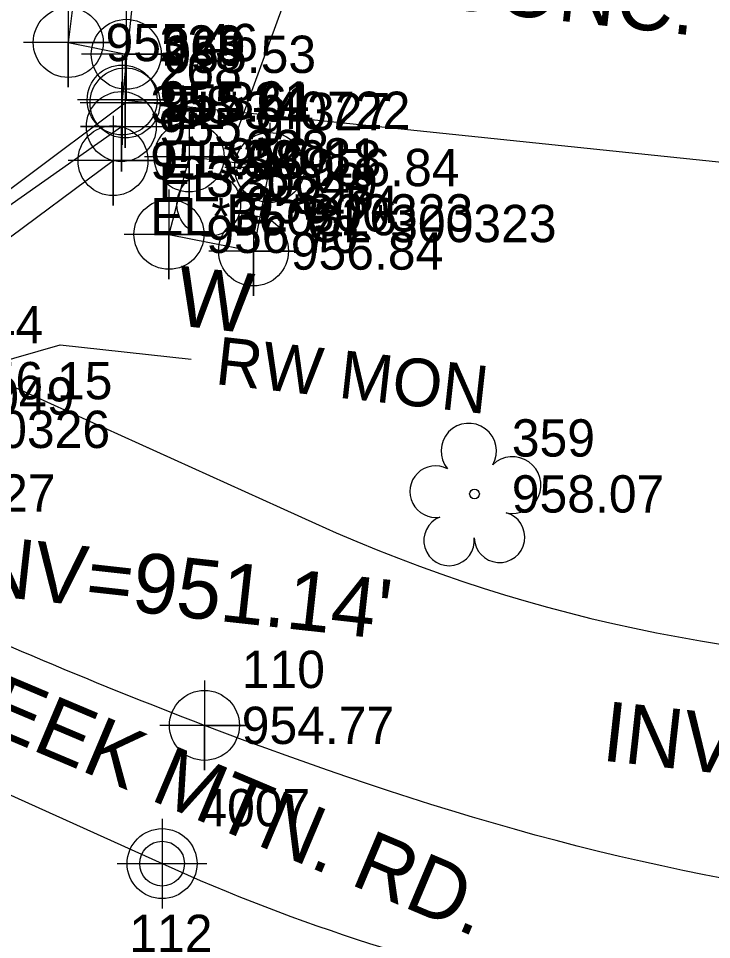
# Model space of a CAD drawing. Extents: x 1150279 to 1151282, y 654632 to 657999.
# Drawn here: x 1150952.8 to 1150999.3, y 657073.4 to 657135.2 of the extents above; entities that cross this region are included whole.
import ezdxf

# ---------------------------------------------------------------- set-up
doc = ezdxf.new("R2010")
doc.units = 0
for name, color, linetype in [('COGO Default Chain', 7, 'Continuous'), ('COGO Default Curve', 7, 'Continuous'), ('Cogo Default Point CELL', 7, 'Continuous'), ('COGO Default Point Number', 7, 'Continuous'), ('Exist Building', 7, 'Continuous'), ('Exist Building Cogo Elevation', 7, 'Continuous'), ('Exist Building Cogo Number', 7, 'Continuous'), ('Exist Building Cogo Point CELL', 7, 'Continuous'), ('Exist Building Steps', 7, 'Continuous'), ('Exist Building Steps Cogo Comment', 7, 'Continuous'), ('Exist Building Steps Cogo Elevation', 7, 'Continuous'), ('Exist Building Steps Cogo Point CELL', 7, 'Continuous'), ('Exist Horizontal Alignment', 7, 'Continuous'), ('Exist Horizontal Alignment Station Label', 7, 'Continuous'), ('Exist Other Culture Well CELL', 7, 'Continuous'), ('Exist Other Culture Well Cogo Elevation', 7, 'Continuous'), ('Exist Other Culture Well Cogo Number', 7, 'Continuous'), ('Exist Other Culture Well Text', 7, 'Continuous'), ('Exist Right of Way Line', 7, 'Continuous'), ('Exist Right of Way Monument Cogo Elevation', 7, 'Continuous'), ('Exist Right of Way Monument Cogo Number', 7, 'Continuous'), ('Exist Right of Way Monument Leader', 7, 'Continuous'), ('Exist Right of Way Monument Text', 7, 'Continuous'), ('Exist Roads Curbs', 7, 'Continuous'), ('Exist Roads Curbs Cogo Comment', 7, 'Continuous'), ('Exist Roads Curbs Cogo Elevation', 7, 'Continuous'), ('Exist Roads Curbs Cogo Number', 7, 'Continuous'), ('Exist Roads Curbs Cogo Point CELL', 7, 'Continuous'), ('Exist Roads EOP', 7, 'Continuous'), ('Exist Roads EOP Cogo Comment', 7, 'Continuous'), ('Exist Roads EOP Cogo Elevation', 7, 'Continuous'), ('Exist Roads EOP Cogo Number', 7, 'Continuous'), ('Exist Roads EOP Cogo Point CELL', 7, 'Continuous'), ('Exist Roads EOP Leader', 7, 'Continuous'), ('Exist Roads EOP Other', 7, 'Continuous'), ('Exist Roads EOP Other Cogo Comment', 7, 'Continuous'), ('Exist Roads EOP Other Cogo Elevation', 7, 'Continuous'), ('Exist Roads EOP Other Cogo Number', 7, 'Continuous'), ('Exist Roads EOP Other Cogo Point CELL', 7, 'Continuous'), ('Exist Roads EOP Text', 7, 'Continuous'), ('Exist Structure Minor Pipes CMP 15 Inch Text', 7, 'Continuous'), ('Exist Structure Minor Pipes CMP 18 Inch Cogo Comment', 7, 'Continuous'), ('Exist Vegetation Hedge Row', 7, 'Continuous'), ('Exist Vegetation Hedge Row Cogo Comment', 7, 'Continuous'), ('Exist Vegetation Hedge Row Cogo Elevation', 7, 'Continuous'), ('Exist Vegetation Hedge Row Cogo Number', 7, 'Continuous'), ('Exist Vegetation Hedge Row Cogo Point CELL', 7, 'Continuous'), ('Exist Vegetation Tree CELL', 7, 'Continuous'), ('Exist Vegetation Tree Cogo Elevation', 7, 'Continuous'), ('Exist Vegetation Tree Cogo Number', 7, 'Continuous')]:
    doc.layers.add(name, color=color, linetype=linetype)

msp = doc.modelspace()

# ---------------------------------------------------------------- linework, layer by layer
at = {"layer": 'COGO Default Chain'}
msp.add_line((1150875.785, 657117.706), (1150962.476, 657078.528), dxfattribs=at)
msp.add_arc((1151016.013, 657196.992), 130, 245.68044, 271.91872, dxfattribs=at)
at = {"layer": 'COGO Default Curve'}
msp.add_arc((1151016.013, 657196.992), 130, 245.68044, 271.91872, dxfattribs=at)
at = {"layer": 'Cogo Default Point CELL'}
for points in [[(1150962.476, 657081.528), (1150962.476, 657078.528)], [(1150962.476, 657081.528), (1150962.476, 657078.528)], [(1150959.476, 657078.528), (1150962.476, 657078.528)], [(1150959.476, 657078.528), (1150962.476, 657078.528)], [(1150962.476, 657078.528), (1150965.476, 657078.528)], [(1150962.476, 657078.528), (1150962.476, 657075.528)], [(1150962.476, 657078.528), (1150965.476, 657078.528)], [(1150962.476, 657078.528), (1150962.476, 657075.528)]]:
    msp.add_lwpolyline(points, dxfattribs=at)
msp.add_circle((1150962.476, 657078.528), 2.344, dxfattribs=at)
msp.add_circle((1150962.476, 657078.528), 2.344, dxfattribs=at)
at = {"layer": 'Exist Building'}
msp.add_lwpolyline([(1150963.173, 657162.304), (1150961.996, 657151.199), (1150955.742, 657152.172), (1150954.56, 657141.15), (1150960.937, 657140.596), (1150959.8, 657129.688), (1151003.45, 657125.164), (1151002.473, 657115.197), (1151037.798, 657111.576), (1151043.238, 657164.141)], dxfattribs=at)
at = {"layer": 'Exist Building Cogo Point CELL'}
msp.add_lwpolyline([(1150959.8, 657132.688), (1150959.8, 657126.688), (1150959.8, 657129.688), (1150962.8, 657129.688), (1150956.8, 657129.688)], dxfattribs=at)
msp.add_circle((1150959.8, 657129.688), 2.344, dxfattribs=at)
at = {"layer": 'Exist Building Steps'}
msp.add_lwpolyline([(1150957.09, 657140.886), (1150956.186, 657133.538), (1150960.076, 657132.748)], dxfattribs=at)
at = {"layer": 'Exist Building Steps Cogo Point CELL'}
for points in [[(1150956.186, 657136.538), (1150956.186, 657130.538), (1150956.186, 657133.538), (1150959.186, 657133.538), (1150953.186, 657133.538)], [(1150960.076, 657135.748), (1150960.076, 657129.748), (1150960.076, 657132.748), (1150963.076, 657132.748), (1150957.076, 657132.748)]]:
    msp.add_lwpolyline(points, dxfattribs=at)
for centre in [(1150956.186, 657133.538), (1150960.076, 657132.748)]:
    msp.add_circle(centre, 2.344, dxfattribs=at)
at = {"layer": 'Exist Horizontal Alignment'}
msp.add_line((1150875.785, 657117.706), (1150962.476, 657078.528), dxfattribs=at)
msp.add_arc((1151016.013, 657196.992), 130, 245.68044, 271.91872, dxfattribs=at)
at = {"layer": 'Exist Horizontal Alignment Station Label'}
msp.add_circle((1150962.476, 657078.528), 1.5, dxfattribs=at)
at = {"layer": 'Exist Other Culture Well CELL'}
msp.add_circle((1150965.603, 657122.692), 2.132, dxfattribs=at)
at = {"layer": 'Exist Right of Way Line'}
msp.add_line((1150947.298, 657112.822), (1150972.772, 657101.31), dxfattribs=at)
msp.add_arc((1151016.013, 657196.992), 105, 245.68044, 271.91872, dxfattribs=at)
at = {"layer": 'Exist Right of Way Monument Leader'}
msp.add_lwpolyline([(1150946.455, 657110.649), (1150955.645, 657113.292), (1150964.436, 657112.319)], dxfattribs=at)
at = {"layer": 'Exist Roads Curbs'}
msp.add_line((1150939.414, 657113.606), (1150959.746, 657127.905), dxfattribs=at)
at = {"layer": 'Exist Roads Curbs Cogo Point CELL'}
msp.add_lwpolyline([(1150959.746, 657130.905), (1150959.746, 657124.905), (1150959.746, 657127.905), (1150957.016, 657127.905), (1150962.746, 657127.905)], dxfattribs=at)
msp.add_circle((1150959.746, 657127.905), 2.344, dxfattribs=at)
at = {"layer": 'Exist Roads EOP'}
msp.add_lwpolyline([(1150929.365, 657106.111), (1150938.865, 657113.677), (1150959.994, 657129.491)], dxfattribs=at)
for points in [[(1151056.232, 657077.091), (1151010.245, 657076.049), (1150965.316, 657087.792), (1150920.52, 657109.03), (1150919.164, 657109.821)], [(1151056.975, 657058.926), (1151008.048, 657058.299), (1150957.779, 657070.103), (1150911.093, 657090.114), (1150910.091, 657090.545)]]:
    msp.add_spline(points, degree=3, dxfattribs=at)
at = {"layer": 'Exist Roads EOP Cogo Point CELL'}
for points in [[(1150959.994, 657132.491), (1150959.994, 657126.491), (1150959.994, 657129.491), (1150962.994, 657129.491), (1150956.994, 657129.491)], [(1150965.316, 657090.792), (1150965.316, 657084.792), (1150965.316, 657087.792), (1150968.316, 657087.792), (1150962.316, 657087.792)]]:
    msp.add_lwpolyline(points, dxfattribs=at)
for centre in [(1150959.994, 657129.491), (1150965.316, 657087.792)]:
    msp.add_circle(centre, 2.344, dxfattribs=at)
at = {"layer": 'Exist Roads EOP Leader'}
msp.add_lwpolyline([(1150966.81, 657125.701), (1150971.617, 657138.864), (1150979.775, 657137.961)], dxfattribs=at)
at = {"layer": 'Exist Roads EOP Other'}
msp.add_lwpolyline([(1150964.287, 657125.875), (1150962.937, 657120.687), (1150968.604, 657119.571), (1150969.691, 657125.162), (1150964.287, 657125.875)], dxfattribs=at)
at = {"layer": 'Exist Roads EOP Other Cogo Point CELL'}
for points in [[(1150964.287, 657128.875), (1150964.287, 657122.875), (1150964.287, 657125.875), (1150967.287, 657125.875), (1150961.287, 657125.875)], [(1150969.691, 657128.162), (1150969.691, 657122.162), (1150969.691, 657125.162), (1150972.691, 657125.162), (1150966.691, 657125.162)], [(1150962.937, 657123.687), (1150962.937, 657117.687), (1150962.937, 657120.687), (1150965.937, 657120.687), (1150959.937, 657120.687)], [(1150968.604, 657122.571), (1150968.604, 657116.571), (1150968.604, 657119.571), (1150971.604, 657119.571), (1150965.604, 657119.571)]]:
    msp.add_lwpolyline(points, dxfattribs=at)
for centre in [(1150964.287, 657125.875), (1150969.691, 657125.162), (1150962.937, 657120.687), (1150968.604, 657119.571)]:
    msp.add_circle(centre, 2.344, dxfattribs=at)
at = {"layer": 'Exist Vegetation Hedge Row'}
msp.add_line((1150939.948, 657111.372), (1150959.188, 657125.623), dxfattribs=at)
at = {"layer": 'Exist Vegetation Hedge Row Cogo Point CELL'}
msp.add_lwpolyline([(1150959.188, 657128.623), (1150959.188, 657122.623), (1150959.188, 657125.623), (1150962.188, 657125.623), (1150956.188, 657125.623)], dxfattribs=at)
msp.add_circle((1150959.188, 657125.623), 2.344, dxfattribs=at)
at = {"layer": 'Exist Vegetation Tree CELL'}
msp.add_line((1150983.421, 657103.298), (1150983.421, 657103.298), dxfattribs=at)
msp.add_circle((1150983.421, 657103.298), 0.326, dxfattribs=at)
for centre, radius, start, end in [((1150983.036, 657106.171), 1.856, 330.16508, 219.71335), ((1150985.97, 657103.886), 1.899, 257.1011, 134.19993), ((1150980.815, 657103.452), 1.727, 62.66361, 279.3457), ((1150985.094, 657100.398), 1.698, 181.28216, 74.55999), ((1150981.717, 657100.177), 1.689, 111.56708, 6.23104)]:
    msp.add_arc(centre, radius, start, end, dxfattribs=at)

# ---------------------------------------------------------------- texts
at = {"layer": 'COGO Default Point Number'}
msp.add_text('4007', height=2.5, dxfattribs=at).set_placement((1150964.976, 657081.028))
at = {"layer": 'Exist Building Cogo Elevation'}
msp.add_text('955.61', height=2.5, dxfattribs=at).set_placement((1150962.3, 657128.438))
at = {"layer": 'Exist Building Cogo Number'}
msp.add_text('323', height=2.5, dxfattribs=at).set_placement((1150962.3, 657132.188))
at = {"layer": 'Exist Building Steps Cogo Comment'}
msp.add_text('EL*340722', height=2.5, dxfattribs=at).set_placement((1150962.576, 657127.748))
at = {"layer": 'Exist Building Steps Cogo Elevation'}
for s, p in [('955.46', (1150958.686, 657132.288)), ('955.53', (1150962.576, 657131.498))]:
    msp.add_text(s, height=2.5, dxfattribs=at).set_placement(p)
at = {"layer": 'Exist Other Culture Well Cogo Elevation'}
msp.add_text('956.74', height=2.5, dxfattribs=at).set_placement((1150968.099, 657121.438))
at = {"layer": 'Exist Other Culture Well Cogo Number'}
msp.add_text('328', height=2.5, dxfattribs=at).set_placement((1150968.099, 657125.188))
at = {"layer": 'Exist Other Culture Well Text'}
msp.add_text('W', height=4, rotation=353.6867, dxfattribs=at).set_placement((1150963.294, 657114.609))
at = {"layer": 'Exist Right of Way Monument Cogo Elevation'}
msp.add_text('956.15', height=2.5, dxfattribs=at).set_placement((1150948.922, 657109.635))
at = {"layer": 'Exist Right of Way Monument Cogo Number'}
msp.add_text('344', height=2.5, dxfattribs=at).set_placement((1150948.922, 657113.385))
at = {"layer": 'Exist Right of Way Monument Text'}
msp.add_text('RW MON', height=3.2, rotation=353.6867, dxfattribs=at).set_placement((1150965.97, 657110.662))
at = {"layer": 'Exist Roads Curbs Cogo Comment'}
for s, p in [('EL*30049', (1150962.246, 657122.905)), ('BL*30049', (1150941.914, 657108.606))]:
    msp.add_text(s, height=2.5, dxfattribs=at).set_placement(p)
at = {"layer": 'Exist Roads Curbs Cogo Elevation'}
msp.add_text('955.91', height=2.5, dxfattribs=at).set_placement((1150962.246, 657126.655))
at = {"layer": 'Exist Roads Curbs Cogo Number'}
msp.add_text('268', height=2.5, dxfattribs=at).set_placement((1150962.246, 657130.405))
at = {"layer": 'Exist Roads EOP Cogo Comment'}
msp.add_text('EL*30018', height=2.5, dxfattribs=at).set_placement((1150962.494, 657124.491))
at = {"layer": 'Exist Roads EOP Cogo Elevation'}
for s, p in [('955.61', (1150962.494, 657128.241)), ('954.77', (1150967.816, 657086.542))]:
    msp.add_text(s, height=2.5, dxfattribs=at).set_placement(p)
at = {"layer": 'Exist Roads EOP Cogo Number'}
for s, p in [('269', (1150962.494, 657131.991)), ('110', (1150967.816, 657090.292)), ('112', (1150960.279, 657072.603))]:
    msp.add_text(s, height=2.5, dxfattribs=at).set_placement(p)
at = {"layer": 'Exist Roads EOP Other Cogo Comment'}
for s, p in [('BL*300323', (1150966.787, 657120.875)), ('CL*300323', (1150972.191, 657120.162))]:
    msp.add_text(s, height=2.5, dxfattribs=at).set_placement(p)
at = {"layer": 'Exist Roads EOP Other Cogo Elevation'}
for s, p in [('956.81', (1150966.787, 657124.625)), ('956.84', (1150972.191, 657123.912)), ('956.70', (1150965.437, 657119.437)), ('956.84', (1150971.104, 657118.321))]:
    msp.add_text(s, height=2.5, dxfattribs=at).set_placement(p)
at = {"layer": 'Exist Roads EOP Other Cogo Number'}
for s, p in [('324', (1150966.787, 657128.375)), ('327', (1150972.191, 657127.662)), ('325', (1150965.437, 657123.187)), ('326', (1150971.104, 657122.071))]:
    msp.add_text(s, height=2.5, dxfattribs=at).set_placement(p)
at = {"layer": 'Exist Roads EOP Text'}
for s, rotation, p in [('CONC. PAD', 353.6867, (1150980.944, 657135.901)), ('CANE CREEK MTN. RD.', 337.10646, (1150928.179, 657096.94))]:
    msp.add_text(s, height=4, rotation=rotation, dxfattribs=at).set_placement(p)
at = {"layer": 'Exist Structure Minor Pipes CMP 15 Inch Text'}
for s, p in [("INV=951.14'", (1150948.372, 657096.768)), ("INV=957.10'", (1150991.875, 657085.443))]:
    msp.add_text(s, height=4, rotation=353.6867, dxfattribs=at).set_placement(p)
at = {"layer": 'Exist Structure Minor Pipes CMP 18 Inch Cogo Comment'}
msp.add_text('BL*521827', height=2.5, dxfattribs=at).set_placement((1150938.788, 657102.106))
at = {"layer": 'Exist Vegetation Hedge Row Cogo Comment'}
for s, p in [('EL*360326', (1150961.688, 657120.623)), ('BL*360326', (1150942.448, 657106.372))]:
    msp.add_text(s, height=2.5, dxfattribs=at).set_placement(p)
at = {"layer": 'Exist Vegetation Hedge Row Cogo Elevation'}
msp.add_text('955.98', height=2.5, dxfattribs=at).set_placement((1150961.688, 657124.373))
at = {"layer": 'Exist Vegetation Hedge Row Cogo Number'}
msp.add_text('358', height=2.5, dxfattribs=at).set_placement((1150961.688, 657128.123))
at = {"layer": 'Exist Vegetation Tree Cogo Elevation'}
msp.add_text('958.07', height=2.5, dxfattribs=at).set_placement((1150985.921, 657102.048))
at = {"layer": 'Exist Vegetation Tree Cogo Number'}
msp.add_text('359', height=2.5, dxfattribs=at).set_placement((1150985.921, 657105.798))

doc.saveas('drawing.dxf')
